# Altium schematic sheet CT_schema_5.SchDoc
size 510 x 408 mm
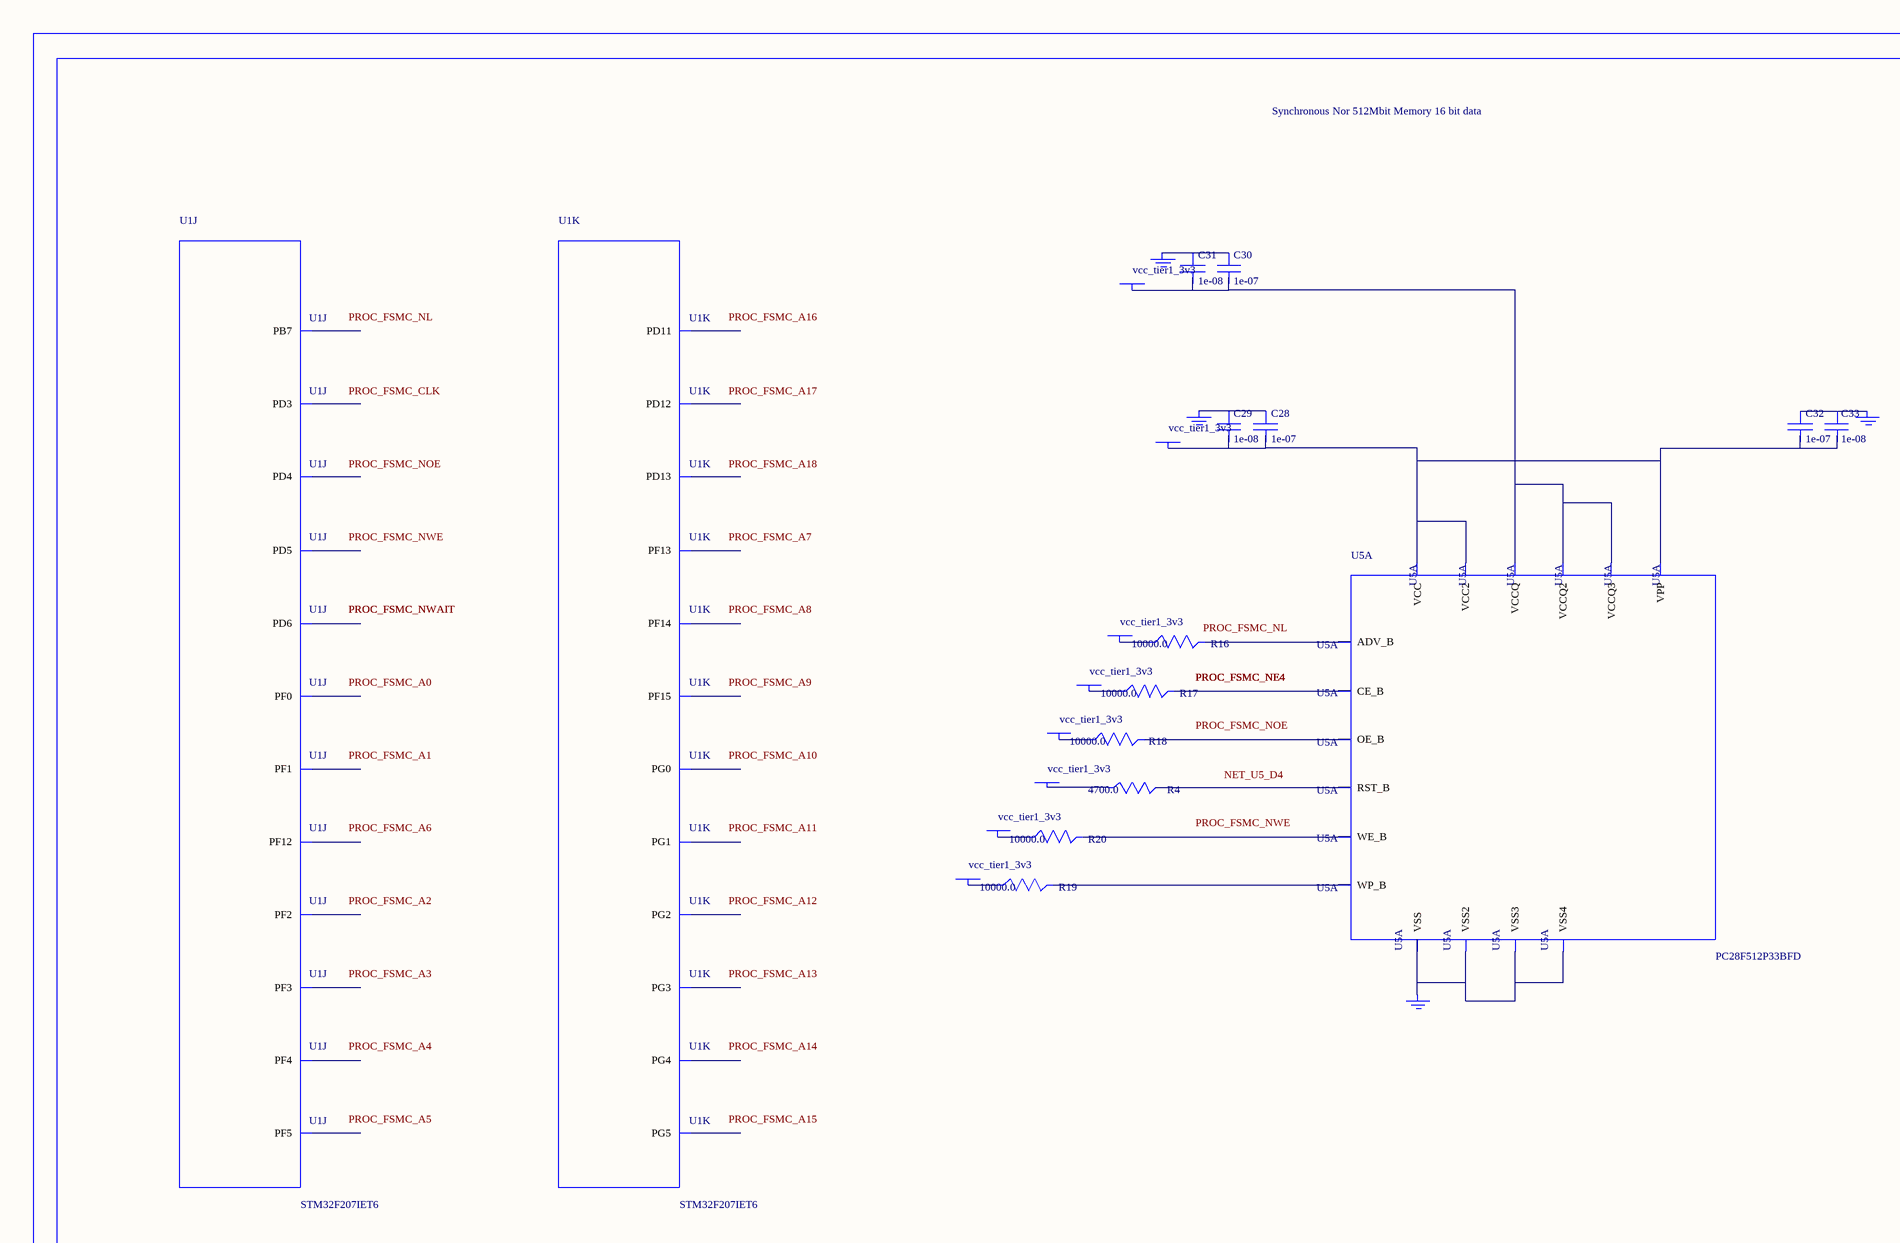
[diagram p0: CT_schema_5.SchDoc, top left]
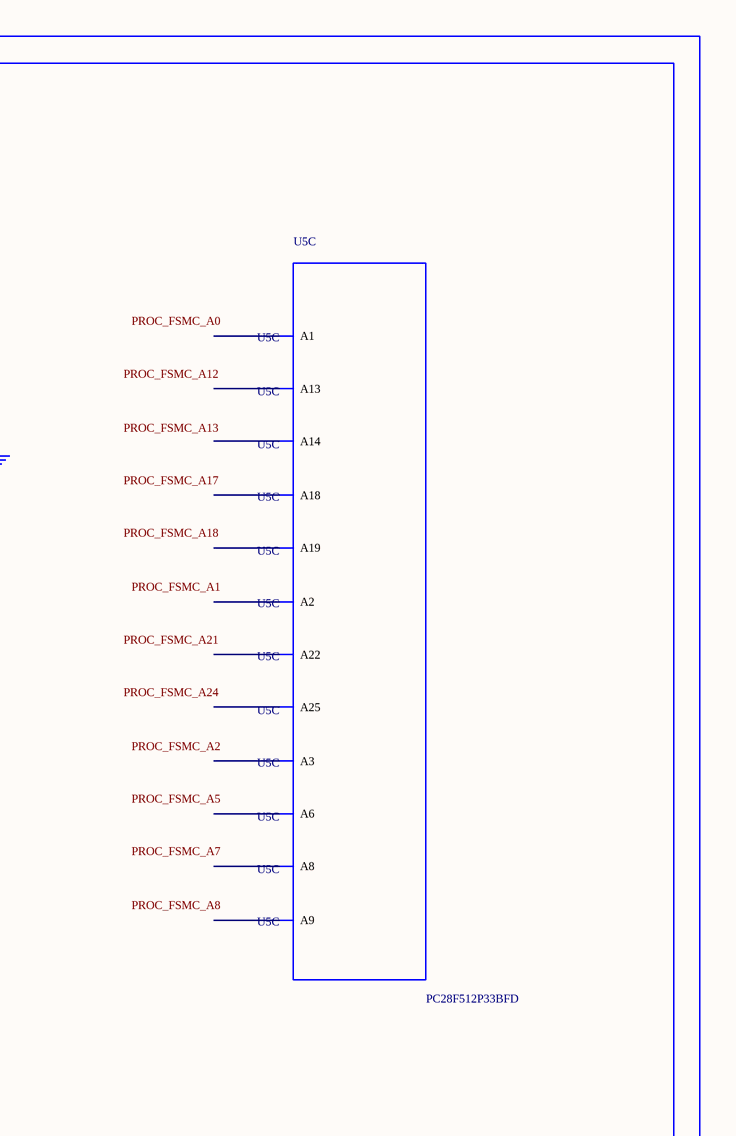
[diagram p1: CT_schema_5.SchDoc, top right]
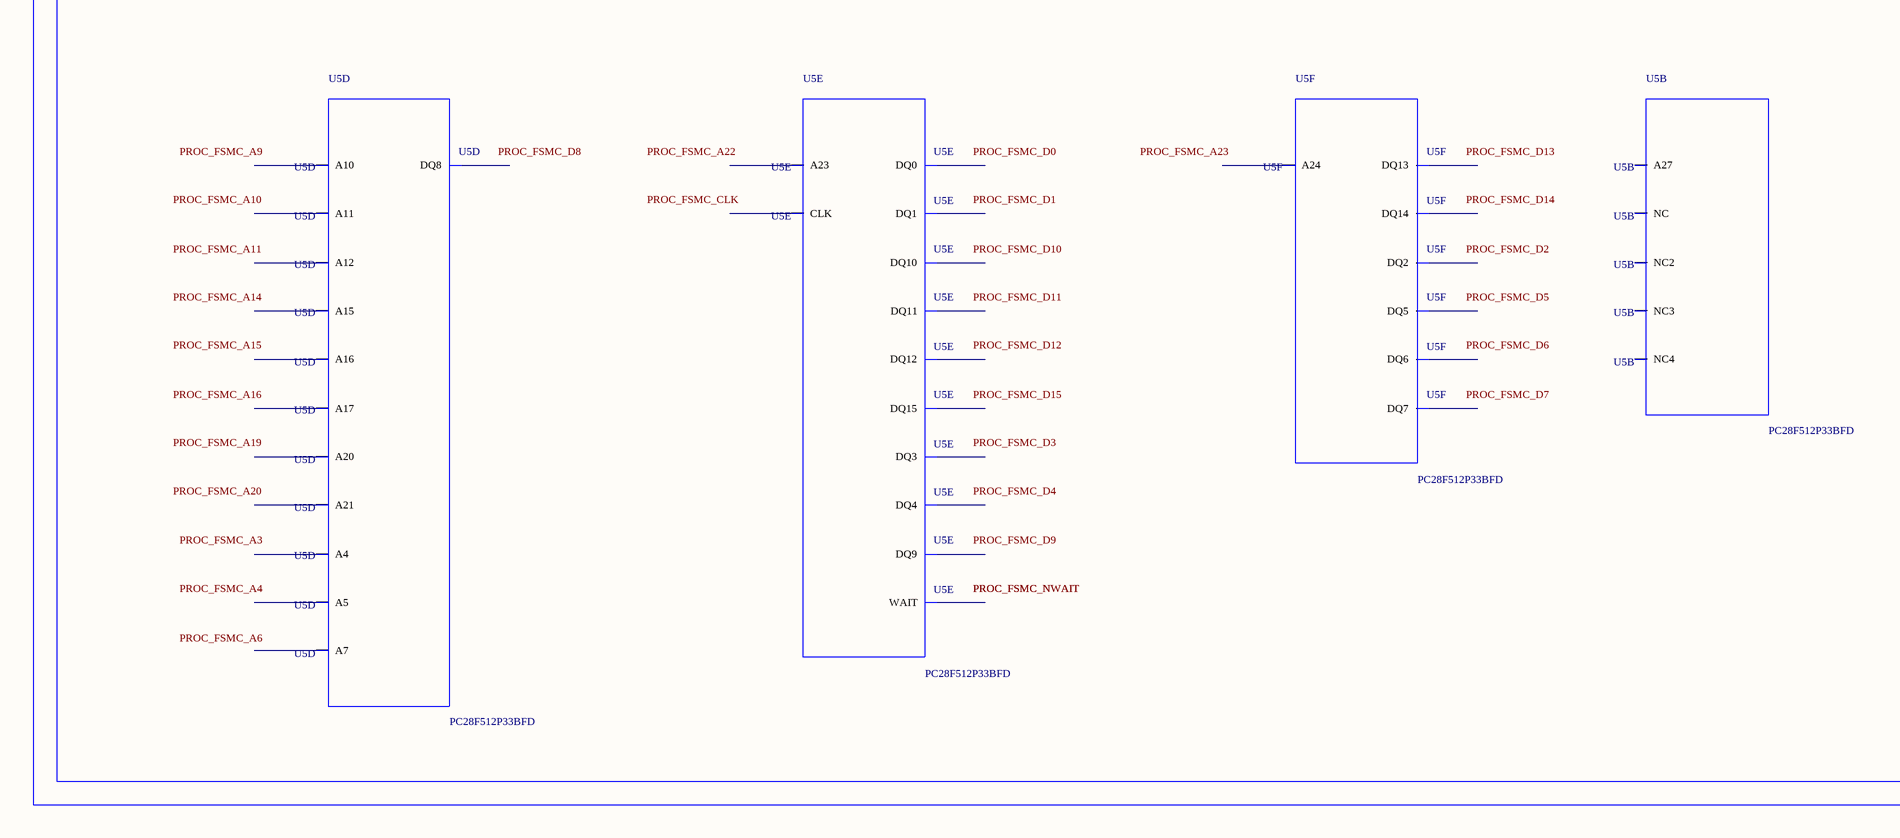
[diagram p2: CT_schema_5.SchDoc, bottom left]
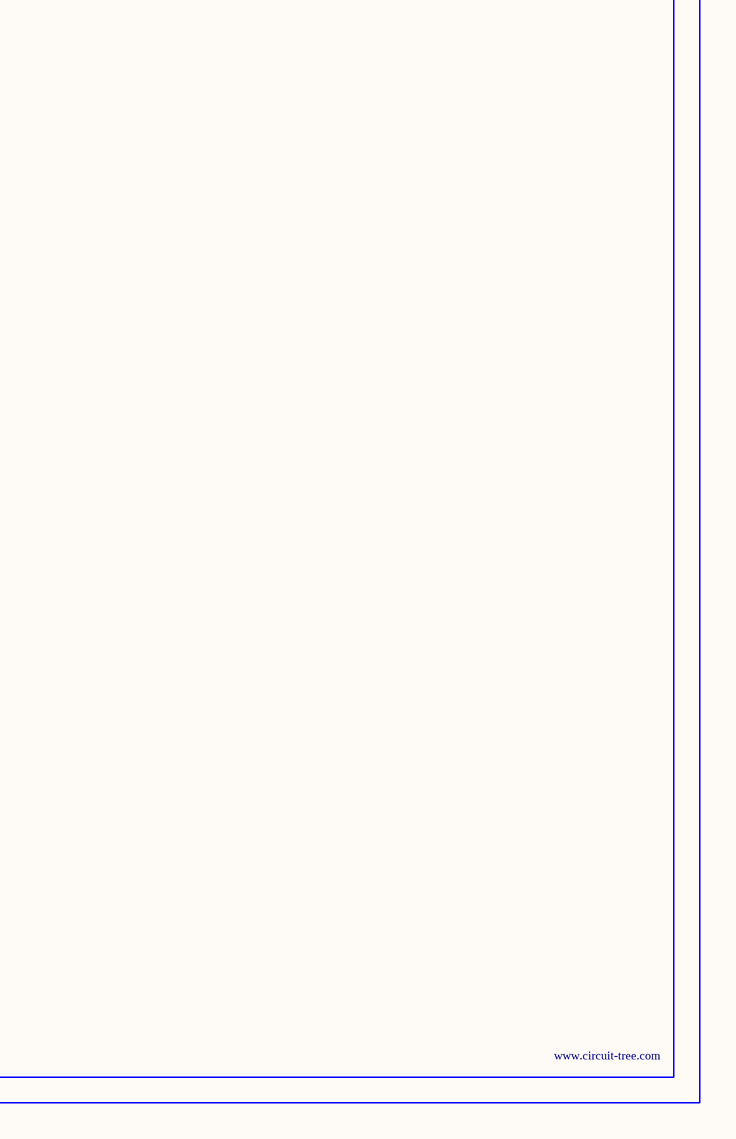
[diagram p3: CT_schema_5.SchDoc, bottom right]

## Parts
BORDER4  (no value)
C28  1e-07  [C0402]
C29  1e-08  [C0402]
C30  1e-07  [C0402]
C31  1e-08  [C0402]
C32  1e-07  [C0402]
C33  1e-08  [C0402]
GND_INSTANCE_4_0  (no value)
GND_INSTANCE_4_1  (no value)
GND_INSTANCE_4_2  (no value)
GND_INSTANCE_4_3  (no value)
POWER_INSTANCE_4_0  vcc_tier1_3v3
POWER_INSTANCE_4_1  vcc_tier1_3v3
POWER_INSTANCE_4_2  vcc_tier1_3v3
POWER_INSTANCE_4_3  vcc_tier1_3v3
POWER_INSTANCE_4_4  vcc_tier1_3v3
POWER_INSTANCE_4_5  vcc_tier1_3v3
POWER_INSTANCE_4_6  vcc_tier1_3v3
POWER_INSTANCE_4_7  vcc_tier1_3v3
R4  4700.0  [R0603]
R16  10000.0  [R0603]
R17  10000.0  [R0603]
R18  10000.0  [R0603]
R19  10000.0  [R0603]
R20  10000.0  [R0603]
U1  STM32F207IET6  [LQFP176]  (parts J,K of 11)
U5  PC28F512P33BFD  [PC28F512P33BFD]  (parts A,B,C,D,E,F of 6)

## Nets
NetC28_1: C28.1 C29.1 GND_INSTANCE_4_0.0(GND)
NetC28_2: C28.2 C29.2 C32.2 C33.2 POWER_INSTANCE_4_0.0(PWR) U5.A4(VPP) U5.A6(VCC) U5.H3(VCC2)
NetC30_1: C30.1 C31.1 GND_INSTANCE_4_1.0(GND)
NetC30_2: C30.2 C31.2 POWER_INSTANCE_4_1.0(PWR) U5.D5(VCCQ) U5.D6(VCCQ2) U5.G4(VCCQ3)
NetC32_1: C32.1 C33.1 GND_INSTANCE_4_2.0(GND)
NetGND_INSTANCE_4_3_0: GND_INSTANCE_4_3.0(GND) U5.B2(VSS) U5.H2(VSS2) U5.H4(VSS3) U5.H6(VSS4)
NetPOWER_INSTANCE_4_2_0: POWER_INSTANCE_4_2.0(PWR) R16.1
NetPOWER_INSTANCE_4_3_0: POWER_INSTANCE_4_3.0(PWR) R17.1
NetPOWER_INSTANCE_4_4_0: POWER_INSTANCE_4_4.0(PWR) R18.1
NetPOWER_INSTANCE_4_5_0: POWER_INSTANCE_4_5.0(PWR) R19.1
NetPOWER_INSTANCE_4_6_0: POWER_INSTANCE_4_6.0(PWR) R20.1
NetPOWER_INSTANCE_4_7_0: POWER_INSTANCE_4_7.0(PWR) R4.1
NetR4_2: R4.2 U5.D4(RST_B)
NetR16_2: R16.2 U5.F6(ADV_B)
NetR17_2: R17.2 U5.B4(CE_B)
NetR18_2: R18.2 U5.F8(OE_B)
NetR19_2: R19.2 U5.C6(WP_B)
NetR20_2: R20.2 U5.G8(WE_B)

Not connected (* = marked no-connect by the designer): U1 16(PF0) 17(PF1) 18(PF2) 19(PF3) 20(PF4) 21(PF5) 60(PF12) 63(PF13) 64(PF14) 65(PF15) 66(PG0) 67(PG1) 99(PD11) 100(PD12) 101(PD13) 106(PG2) 107(PG3) 108(PG4) 109(PG5) 145(PD3) 146(PD4) 147(PD5) 150(PD6) 165(PB7); U5 A1 A2(A6) A3(A8) A5(A13) A7(A18) A8(A22) B1(A2) B3(A9) B5(A14) B6(A25) B7(A19) B8(NC) C1(A3) C2(A7) C3(A10) C4(A12) C5(A15) C7(A20) C8(A21) D1(A4) D2(A5) D3(A11) D7(A16) D8(A17) E1(DQ8) E2(DQ1) E3(DQ9) E4(DQ3) E5(DQ4) E6(CLK) E7(DQ15) E8(NC2) F1(NC3) F2(DQ0) F3(DQ10) F4(DQ11) F5(DQ12) F7(WAIT) G1(A23) G2(NC4) G3(DQ2) G5(DQ5) G6(DQ6) G7(DQ14) H1(A27) H5(DQ13) H7(DQ7) H8(A24)

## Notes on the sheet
- Labels drawn without touching a wire or pin: NET_U5_D4, PROC_FSMC_A0, PROC_FSMC_A1, PROC_FSMC_A2, PROC_FSMC_A3, PROC_FSMC_A4, PROC_FSMC_A5, PROC_FSMC_A6, PROC_FSMC_A7, PROC_FSMC_A8, PROC_FSMC_A9, PROC_FSMC_A10, PROC_FSMC_A11, PROC_FSMC_A12, PROC_FSMC_A13, PROC_FSMC_A14, PROC_FSMC_A15, PROC_FSMC_A16, PROC_FSMC_A17, PROC_FSMC_A18, PROC_FSMC_A19, PROC_FSMC_A20, PROC_FSMC_A21, PROC_FSMC_A22, PROC_FSMC_A23, PROC_FSMC_A24, PROC_FSMC_CLK, PROC_FSMC_D0, PROC_FSMC_D1, PROC_FSMC_D2, PROC_FSMC_D3, PROC_FSMC_D4, PROC_FSMC_D5, PROC_FSMC_D6, PROC_FSMC_D7, PROC_FSMC_D8, PROC_FSMC_D9, PROC_FSMC_D10, PROC_FSMC_D11, PROC_FSMC_D12, PROC_FSMC_D13, PROC_FSMC_D14, PROC_FSMC_D15, PROC_FSMC_NL, PROC_FSMC_NOE, PROC_FSMC_NWE

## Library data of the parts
BORDER4 = BORDER_PAGE4
C28 C30 C32 = C0402C104K3RACTU
C29 C31 C33 = C0402C103K3RAC
GND_INSTANCE_4_0-GND_INSTANCE_4_3 = GND
POWER_INSTANCE_4_0-POWER_INSTANCE_4_7 = PWR
R4 = RC0603JR-074K7L
R16-R20 = RC0603JR-0710KL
